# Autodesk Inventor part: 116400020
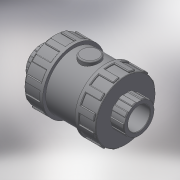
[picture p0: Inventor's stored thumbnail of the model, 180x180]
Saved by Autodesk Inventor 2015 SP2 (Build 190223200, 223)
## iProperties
Created: 2017-11
Part Number: 116400020
Material: Generic
Description: PLASSON FOOT VALVE CEM PVC 20
Document SubType Name: Modeling
Designer: KIM
Density: 1 g/cm^3
Appearance: Default
Author: KIM
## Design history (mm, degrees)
derived "116400 - 116000.ipt"
feature "Solid1::116400 - 116000.ipt"
tag "TaggingFeature1"
body "Solid1"
other parameters: "d0" = 75, "d2" = 45, "d3" = 16, "d4" = 16, "d5" = 11.2, "d7" = 28, "d8" = 40.5, "d13" = 0.6, "d23" = 16, "d24" = 43.2, "d25" = 0.4, "d26" = 0.6, "d27" = 6.75, "d28" = 3.375, "d29" = 12, "d30" = 0, "d35" = 0.6, "d39" = 22.5, "d45" = 360 deg, "d47" = 0.4, "d50" = 22.5, "d51" = 13.5, "d53" = 0, "d54" = 0.9, "d56" = 4, "d57" = 2, "d59" = 0, "d60" = 0.6, "d62" = 360 deg, "l_" = 16, "H_" = 75, "K_" = 45
